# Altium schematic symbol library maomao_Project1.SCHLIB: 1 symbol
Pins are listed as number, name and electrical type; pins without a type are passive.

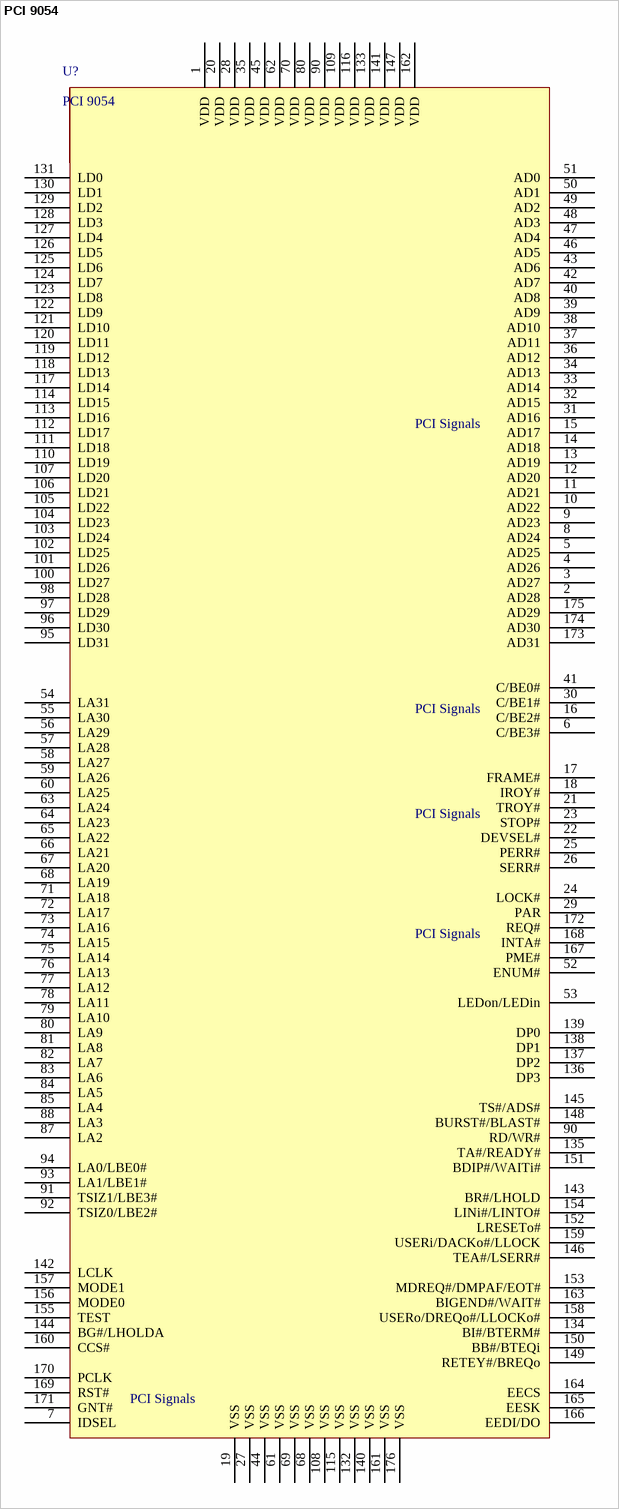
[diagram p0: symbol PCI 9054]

## PCI 9054
designator U?
pins: 1 VDD, 2 AD28, 3 AD27, 4 AD26, 5 AD25, 6 C/BE3#, 7 IDSEL, 8 AD24, 9 AD23, 10 AD22, 11 AD21, 12 AD20, 13 AD19, 14 AD18, 15 AD17, 16 C/BE2#, 17 FRAME#, 18 IROY#, 19 VSS, 20 VDD, 21 TROY#, 22 DEVSEL#, 23 STOP#, 24 LOCK#, 25 PERR#, 26 SERR#, 27 VSS, 28 VDD, 29 PAR, 30 C/BE1#, 31 AD16, 32 AD15, 33 AD14, 34 AD13, 35 VDD, 36 AD12, 37 AD11, 38 AD10, 39 AD9, 40 AD8, 41 C/BE0#, 42 AD7, 43 AD6, 44 VSS, 45 VDD, 46 AD5, 47 AD4, 48 AD3, 49 AD2, 50 AD1, 51 AD0, 52 ENUM#, 53 LEDon/LEDin, 54 LA31, 55 LA30, 56 LA29, 57 LA28, 58 LA27, 59 LA26, 60 LA25, 61 VSS, 62 VDD, 63 LA24, 64 LA23, 65 LA22, 66 LA21, 67 LA20, 68 VSS, 68 LA19, 69 VSS, 70 VDD, 71 LA18, 72 LA17, 73 LA16, 74 LA15, 75 LA14, 76 LA13, 77 LA12, 78 LA11, 79 LA10, 80 VDD, 80 LA9, 81 LA8, 82 LA7, 83 LA6, 84 LA5, 85 LA4, 87 LA2, 88 LA3, 90 VDD, 90 RD/WR#, 91 TSIZ1/LBE3#, 92 TSIZ0/LBE2#, 93 LA1/LBE1#, 94 LA0/LBE0#, 95 LD31, 96 LD30, 97 LD29, 98 LD28, 100 LD27, 101 LD26, 102 LD25, 103 LD24, 104 LD23, 105 LD22, 106 LD21, 107 LD20, 108 VSS, 109 VDD, 110 LD19, 111 LD18, 112 LD17, 113 LD16, 114 LD15, 115 VSS, 116 VDD, 117 LD14, 118 LD13, 119 LD12, 120 LD11, 121 LD10, 122 LD9, 123 LD8, 124 LD7, 125 LD6, 126 LD5, 127 LD4, 128 LD3, 129 LD2, 130 LD1, 131 LD0, 132 VSS, 133 VDD, 134 BI#/BTERM#, 135 TA#/READY#, 136 DP3, 137 DP2, 138 DP1, 139 DP0, 140 VSS, 141 VDD, 142 LCLK, 143 BR#/LHOLD, 144 BG#/LHOLDA, 145 TS#/ADS#, 146 TEA#/LSERR#, 147 VDD, 148 BURST#/BLAST#, 149 RETEY#/BREQo, 150 BB#/BTEQi, 151 BDIP#/WAITi#, 152 LRESETo#, 153 MDREQ#/DMPAF/EOT#, 154 LINi#/LINTO#, 155 TEST, 156 MODE0, 157 MODE1, 158 USERo/DREQo#/LLOCKo#, 159 USERi/DACKo#/LLOCK, 160 CCS#, 161 VSS, 162 VDD, 163 BIGEND#/WAIT#, 164 EECS, 165 EESK, 166 EEDI/DO, 167 PME#, 168 INTA#, 169 RST#, 170 PCLK, 171 GNT#, 172 REQ#, 173 AD31, 174 AD30, 175 AD29, 176 VSS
